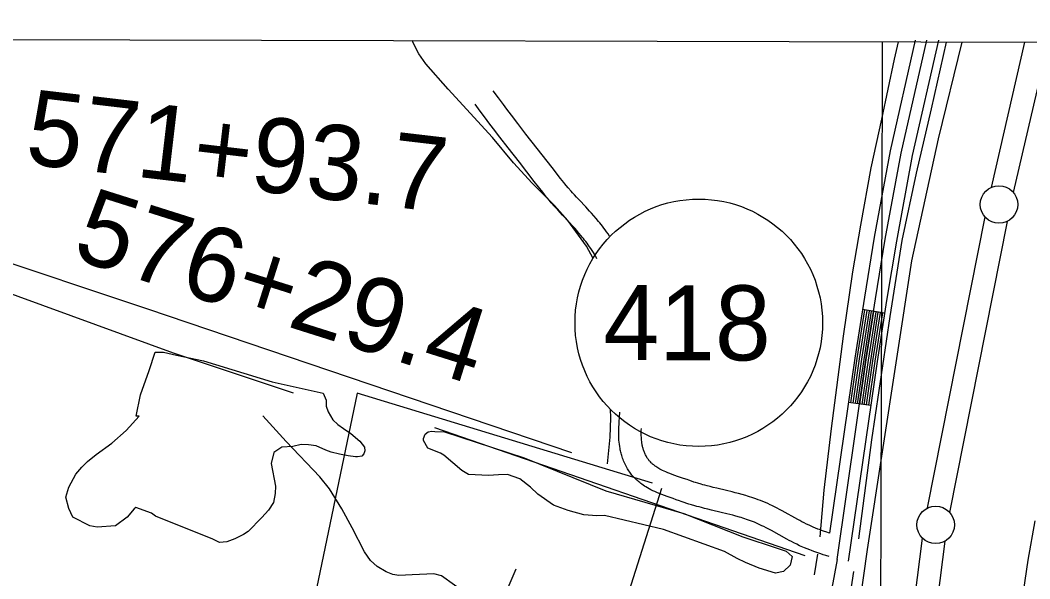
# Model space of a CAD drawing. Extents: x 3161564 to 3199464, y 849354 to 874788.
# Drawn here: x 3175125 to 3176471, y 872262 to 873008 of the extents above; entities that cross this region are included whole.
import ezdxf

# ---------------------------------------------------------------- set-up
doc = ezdxf.new("R2010")
doc.units = 0
for name, color, linetype in [('V-GRID-FRAM', 7, 'Continuous'), ('V-GRID-MAJR', 7, 'Continuous'), ('V-LEVE-TOET', 7, 'Continuous'), ('V-ROAD-CNTR', 7, 'Continuous'), ('V-ROAD-IDEN', 7, 'Continuous'), ('V-SITE-OTLN', 7, 'Continuous'), ('V-SITE-VEGE', 7, 'Continuous'), ('V-SURV-IDEN', 7, 'Continuous'), ('V-SURV-LINE', 7, 'Continuous'), ('V-TOPO-SHOR', 7, 'Continuous')]:
    doc.layers.add(name, color=color, linetype=linetype)

msp = doc.modelspace()

# ---------------------------------------------------------------- linework, layer by layer
at = {"layer": 'V-GRID-FRAM'}
msp.add_lwpolyline([(3165819.245, 873007.562), (3197186.656, 872920.878), (3197144.3310000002, 854733.305), (3165761.0470000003, 854820.033), (3165819.245, 873007.562)], dxfattribs=at)
at = {"layer": 'V-GRID-MAJR'}
msp.add_spline([(3176222.1410000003, 854791.1240000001), (3176239.768, 860850.5530000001), (3176257.404, 866913.068), (3176275.039, 872975.626), (3176275.048, 872978.667)], degree=3, dxfattribs=at)
at = {"layer": 'V-LEVE-TOET'}
for points in [[(3175669.738000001, 869514.5099999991), (3175708.198000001, 869561.856999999), (3175732.372000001, 869595.7699999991), (3175748.332000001, 869623.0369999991), (3175762.058000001, 869648.878999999), (3175775.258000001, 869685.574999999), (3175784.889000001, 869728.035999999), (3175832.198000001, 869934.2939999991), (3175892.899000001, 870206.655999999), (3175926.2690000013, 870366.307999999), (3175967.069000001, 870549.3459999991), (3176018.859000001, 870778.4959999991), (3176047.926000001, 870905.3269999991), (3176080.453000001, 871065.533999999), (3176105.082000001, 871234.712999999), (3176159.337000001, 871580.123999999), (3176184.862000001, 871793.4339999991), (3176216.7690000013, 872030.7399999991), (3176255.034000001, 872301.2399999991), (3176314.084000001, 872686.621999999), (3176349.676000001, 872849.050999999), (3176380.955172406, 872978.3746601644)], [(3176478.148000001, 872339.542999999), (3176468.909000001, 872287.337999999), (3176458.986000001, 872221.037999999), (3176408.313000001, 871944.309999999), (3176379.415000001, 871710.888999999), (3176378.688000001, 871680.0319999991), (3176378.135000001, 871643.724999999), (3176375.205000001, 871570.586999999), (3176373.527000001, 871541.283999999), (3176341.085000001, 871290.329999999), (3176335.283000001, 871235.1249999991), (3176329.973000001, 871198.3509999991), (3176324.869000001, 871172.4659999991), (3176274.335000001, 870917.665999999), (3176234.616000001, 870710.0129999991), (3176228.691000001, 870677.5789999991), (3176219.067000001, 870634.459999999), (3176203.726000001, 870577.062999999), (3176141.878000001, 870249.145999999), (3176018.202000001, 869784.677999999), (3175980.086000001, 869653.8209999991), (3175937.514000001, 869556.466999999)]]:
    msp.add_lwpolyline(points, dxfattribs=at)
at = {"layer": 'V-ROAD-CNTR'}
for p, q in [((3176277.8544074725, 872616.703738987), (3176248.2194667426, 872621.3707296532)), ((3176259.2014447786, 872493.302985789), (3176229.508504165, 872497.584977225))]:
    msp.add_line(p, q, dxfattribs=at)
for points in [[(3176318.6973257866, 872981.0900102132), (3176285.174392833, 872833.2033059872), (3176263.9574352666, 872717.9045365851), (3176250.857461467, 872638.126696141), (3176238.009487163, 872556.535859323), (3176204.363554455, 872323.2053259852)], [(3176214.436534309, 872287.967396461), (3176252.8424574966, 872554.2988637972), (3176265.6674318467, 872635.744700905), (3176278.735405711, 872715.3315417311), (3176299.8713634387, 872830.186312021), (3176334.068295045, 872981.0480102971)], [(3176349.4392643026, 872981.0050103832), (3176314.5683340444, 872827.1693180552), (3176293.513376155, 872712.7585468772), (3176280.4774022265, 872633.3627056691), (3176267.675427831, 872552.0618682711), (3176229.282504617, 872285.826400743)], [(3175911.8898007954, 872718.2979710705), (3175911.0551410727, 872719.5705332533), (3175909.096144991, 872722.4485274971), (3175907.170148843, 872725.183522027), (3175905.2801526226, 872727.7845168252), (3175903.429156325, 872730.2615118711), (3175901.621159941, 872732.6205071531), (3175899.8521634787, 872734.8735026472), (3175898.1271669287, 872737.0244983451), (3175896.426170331, 872739.104494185), (3175893.1701768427, 872742.9864864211), (3175890.075183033, 872746.572479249), (3175887.160188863, 872749.8704726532), (3175884.411194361, 872752.9274665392), (3175879.2992045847, 872758.5034553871), (3175870.4242223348, 872768.0264363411), (3175867.1412289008, 872771.556429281), (3175864.3062345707, 872774.626423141), (3175861.8562394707, 872777.3064177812), (3175859.755243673, 872779.6344131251), (3175856.0932509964, 872783.7704048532), (3175853.419256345, 872786.8713986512), (3175851.449260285, 872789.2093939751), (3175850.0092631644, 872790.9523904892), (3175847.850267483, 872793.6233851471), (3175845.700271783, 872796.3643796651), (3175834.414294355, 872810.9333505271), (3175814.5603340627, 872836.436299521), (3175799.7143637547, 872855.551261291), (3175788.6513858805, 872869.902232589), (3175780.4124023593, 872880.6882110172), (3175774.271414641, 872888.7961948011), (3175769.6984237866, 872894.8801826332), (3175762.8684374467, 872904.0471642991), (3175756.0744510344, 872913.2811458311)], [(3175894.2321747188, 872689.3745936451), (3175893.059177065, 872691.5365893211), (3175892.219178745, 872693.0345863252), (3175890.886181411, 872695.3345817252), (3175889.517184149, 872697.5985771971), (3175887.8051875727, 872700.317571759), (3175886.1091909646, 872702.9025665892), (3175884.4301943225, 872705.3705616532), (3175882.768197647, 872707.7295569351), (3175881.128200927, 872709.988552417), (3175879.5092041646, 872712.1535480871), (3175877.9152073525, 872714.2325439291), (3175876.3502104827, 872716.2275399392), (3175874.811213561, 872718.1465361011), (3175873.322216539, 872719.9685324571), (3175870.322222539, 872723.5425253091), (3175867.4772282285, 872726.8385187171), (3175864.766233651, 872729.9085125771), (3175862.201238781, 872732.7595068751), (3175857.269248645, 872738.139496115), (3175848.468266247, 872747.5844772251), (3175845.139272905, 872751.1624700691), (3175842.212278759, 872754.3304637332), (3175839.650283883, 872757.1364581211), (3175837.3912884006, 872759.6364531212), (3175833.5012961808, 872764.0304443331), (3175830.5873020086, 872767.4094375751), (3175828.4153063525, 872769.9874324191), (3175826.779309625, 872771.9664284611), (3175824.378314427, 872774.937422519), (3175822.0383191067, 872777.922416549), (3175810.7203417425, 872792.5333873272), (3175790.878381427, 872818.0203363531), (3175775.9884112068, 872837.1912980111), (3175764.8514334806, 872851.6382691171), (3175756.5344501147, 872862.5262473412), (3175750.323462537, 872870.7262309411), (3175745.6784718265, 872876.9062185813), (3175738.758485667, 872886.1952000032), (3175731.910499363, 872895.5011813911)], [(3176251.182460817, 872620.903730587), (3176240.976481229, 872556.0888602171), (3176232.4784982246, 872497.1559780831)], [(3176254.146454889, 872620.4367315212), (3176243.942475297, 872555.6408611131), (3176235.4474922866, 872496.7279789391)], [(3176257.109448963, 872619.969732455), (3176246.909469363, 872555.1938620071), (3176238.4164863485, 872496.2989797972)], [(3176260.0734430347, 872619.503733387), (3176249.875463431, 872554.7458629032), (3176241.3864804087, 872495.8709806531)], [(3176263.036437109, 872619.0367343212), (3176252.8424574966, 872554.2988637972), (3176244.3554744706, 872495.442981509)], [(3176265.999431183, 872618.569735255), (3176255.809451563, 872553.851864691), (3176247.3244685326, 872495.0149823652)], [(3176268.963425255, 872618.103736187), (3176258.7754456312, 872553.403865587), (3176250.294462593, 872494.5869832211)], [(3176271.926419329, 872617.6367371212), (3176261.742439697, 872552.9568664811), (3176253.2634566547, 872494.1579840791)], [(3176274.8904134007, 872617.169738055), (3176264.7084337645, 872552.5088673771), (3176256.232450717, 872493.729984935)], [(3175935.0020931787, 872409.1311541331), (3175934.0840950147, 872410.7121509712), (3175933.106096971, 872412.5231473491), (3175932.1690988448, 872414.3841436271), (3175931.310100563, 872416.2011399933), (3175930.514102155, 872417.995136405), (3175929.781103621, 872419.7641328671), (3175929.103104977, 872421.5111293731), (3175928.482106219, 872423.229125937), (3175927.913107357, 872424.9181225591), (3175927.390108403, 872426.5831192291), (3175926.914109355, 872428.2201159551), (3175926.4791102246, 872429.830112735), (3175926.0861110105, 872431.4081095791), (3175925.729111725, 872432.9591064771), (3175925.4051123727, 872434.487103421), (3175925.104112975, 872436.0411003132), (3175924.618113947, 872438.916094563), (3175924.228114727, 872441.7420889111), (3175923.927115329, 872444.459083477), (3175923.7041157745, 872447.0760782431), (3175923.546116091, 872449.5920732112), (3175923.444116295, 872452.0100683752), (3175923.387116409, 872454.3330637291), (3175923.370116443, 872456.5630592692), (3175923.383116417, 872458.7140549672), (3175923.424116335, 872460.8180507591), (3175923.5631160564, 872464.724042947), (3175923.758115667, 872468.3820356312), (3175923.984115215, 872471.785028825), (3175924.4651142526, 872477.9460165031), (3175925.0240227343, 872484.6772464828)], [(3175960.9440412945, 872424.199123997), (3175960.2600426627, 872425.3761216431), (3175959.706043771, 872426.4031195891), (3175959.129044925, 872427.5461173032), (3175958.588046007, 872428.6911150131), (3175958.0880470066, 872429.8211127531), (3175957.625047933, 872430.936110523), (3175957.199048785, 872432.0351083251), (3175956.806049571, 872433.1231061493), (3175956.441050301, 872434.2021039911), (3175956.1080509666, 872435.2671018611), (3175955.800051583, 872436.322099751), (3175955.519052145, 872437.3660976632), (3175955.260052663, 872438.4040955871), (3175955.023053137, 872439.431093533), (3175954.809053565, 872440.447091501), (3175954.6240539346, 872441.399089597), (3175954.274054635, 872443.468085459), (3175954.002055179, 872445.442081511), (3175953.787055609, 872447.385077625), (3175953.624055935, 872449.292073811), (3175953.5060561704, 872451.1660700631), (3175953.428056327, 872453.0060663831), (3175953.385056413, 872454.8150627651), (3175953.370056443, 872456.5910592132), (3175953.381056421, 872458.326055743), (3175953.4140563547, 872459.9900524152), (3175953.510001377, 872462.6876141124)], [(3176204.363554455, 872323.2053259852), (3176199.6255639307, 872324.781322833), (3176197.502568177, 872325.509321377), (3176193.722575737, 872326.860318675), (3176190.928581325, 872327.9013165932), (3176188.862585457, 872328.695315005), (3176185.721591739, 872329.9413125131), (3176182.6045979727, 872331.2253099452), (3176180.7136017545, 872332.0333083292), (3176178.887605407, 872332.8413067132), (3176177.1516088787, 872333.633305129), (3176173.678615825, 872335.2833018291), (3176170.4556222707, 872336.8832986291), (3176167.426628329, 872338.4402955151), (3176164.5736340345, 872339.947292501), (3176161.928639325, 872341.3722896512), (3176141.222680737, 872352.8642666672), (3176138.4946861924, 872354.345263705), (3176133.764695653, 872356.849258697), (3176130.134702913, 872358.7062549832), (3176127.373708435, 872360.0722522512), (3176125.251712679, 872361.0942502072), (3176122.0867190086, 872362.5672472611), (3176118.859725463, 872364.0012443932), (3176115.5817320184, 872365.384241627), (3176112.3907384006, 872366.6602390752), (3176109.297744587, 872367.8372367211), (3176106.2977505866, 872368.9272345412), (3176103.390756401, 872369.936232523), (3176100.5707620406, 872370.876230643), (3176097.838767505, 872371.7502288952), (3176095.1937727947, 872372.5672272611), (3176092.6047779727, 872373.3402257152), (3176087.685787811, 872374.743222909), (3176083.0527970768, 872375.9982203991), (3176078.7198057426, 872377.1232181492), (3176074.6548138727, 872378.1442161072), (3176067.1318289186, 872379.972212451), (3176054.075855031, 872383.081206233), (3176049.2488646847, 872384.2512038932), (3176045.0588730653, 872385.2932018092), (3176041.421880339, 872386.2241999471), (3176038.262886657, 872387.057198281), (3176035.516892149, 872387.805196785), (3176033.152896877, 872388.4681954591), (3176028.9729052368, 872389.6881930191), (3176025.895911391, 872390.6321911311), (3176023.6329159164, 872391.3541896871), (3176020.2039227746, 872392.497187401), (3176016.734929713, 872393.7181849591), (3176014.4219343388, 872394.5461833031), (3176009.8409435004, 872396.140180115), (3176005.5649520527, 872397.6031771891), (3176001.6189599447, 872398.9581744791), (3175997.9909672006, 872400.2311719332), (3175994.6599738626, 872401.439169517), (3175991.6139799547, 872402.5931672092), (3175988.834985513, 872403.7011649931), (3175986.303990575, 872404.7671628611), (3175984.0009951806, 872405.795160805), (3175981.909999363, 872406.7851588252), (3175980.0120031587, 872407.7401569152), (3175978.2880066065, 872408.659155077), (3175976.730009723, 872409.540153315), (3175975.314012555, 872410.3901516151), (3175974.0310151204, 872411.2031499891), (3175972.866017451, 872411.9831484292), (3175971.808019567, 872412.7291469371), (3175970.849021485, 872413.4411455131), (3175969.969023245, 872414.1261441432), (3175969.1720248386, 872414.7771428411), (3175968.4440262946, 872415.3981415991), (3175967.7790276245, 872415.9891404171), (3175967.174028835, 872416.5501392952), (3175966.669029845, 872417.0371383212), (3175965.6010319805, 872418.126136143), (3175964.755033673, 872419.0491342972), (3175964.0460350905, 872419.8741326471), (3175963.4410363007, 872420.6191311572), (3175962.9260373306, 872421.286129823), (3175962.5320381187, 872421.8211287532), (3175961.7370397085, 872422.964126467), (3175961.205040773, 872423.7841248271), (3175960.748041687, 872424.526123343)], [(3176203.700555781, 872292.1113881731), (3176199.607563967, 872293.304385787), (3176195.9575712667, 872294.424383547), (3176192.783577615, 872295.4403815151), (3176190.0215831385, 872296.3593796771), (3176187.586588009, 872297.195378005), (3176183.436596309, 872298.6783750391), (3176180.310602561, 872299.843372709), (3176177.952607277, 872300.7493708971), (3176174.4776142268, 872302.1273681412), (3176170.9966211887, 872303.561365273), (3176168.749625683, 872304.521363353), (3176166.589630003, 872305.4773614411), (3176164.4856342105, 872306.4373595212), (3176160.572642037, 872308.2973558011), (3176156.927649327, 872310.1053521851), (3176153.562656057, 872311.8363487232), (3176150.453662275, 872313.4773454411), (3176147.5326681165, 872315.0523422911), (3176126.7907096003, 872326.564319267), (3176124.320714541, 872327.9033165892), (3176119.914723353, 872330.2373119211), (3176116.6507298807, 872331.906308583), (3176114.2097347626, 872333.1143061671), (3176112.4137383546, 872333.980304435), (3176109.666743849, 872335.2573018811), (3176106.9357493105, 872336.471299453), (3176104.179754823, 872337.634297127), (3176101.484760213, 872338.712294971), (3176098.843765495, 872339.7172929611), (3176096.257770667, 872340.655291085), (3176093.7267757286, 872341.5342893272), (3176091.254780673, 872342.3582876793), (3176088.838785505, 872343.1322861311), (3176086.477790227, 872343.861284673), (3176084.2007947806, 872344.5402833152), (3176079.6498038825, 872345.8392807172), (3176075.360812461, 872347.0002783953), (3176071.293820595, 872348.0572762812), (3176067.458828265, 872349.0202743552), (3176060.115842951, 872350.804270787), (3176047.065869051, 872353.9112645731), (3176042.0968789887, 872355.117262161), (3176037.7228877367, 872356.203259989), (3176033.873895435, 872357.188258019), (3176030.492902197, 872358.081256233), (3176027.526908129, 872358.889254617), (3176024.9009133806, 872359.6242531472), (3176020.3709224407, 872360.948250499), (3176016.937929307, 872362.000248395), (3176014.330934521, 872362.832246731), (3176010.4799422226, 872364.1152441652), (3176006.7009497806, 872365.446241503), (3176004.4399543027, 872366.254239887), (3176000.0549630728, 872367.780236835), (3175995.8369715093, 872369.2232339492), (3175991.780979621, 872370.616231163), (3175987.9069873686, 872371.975228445), (3175984.2279947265, 872373.3112257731), (3175980.744001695, 872374.6312231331), (3175977.4570082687, 872375.9412205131), (3175974.3660144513, 872377.2432179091), (3175971.467020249, 872378.5372153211), (3175968.7500256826, 872379.823212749), (3175966.210030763, 872381.100210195), (3175963.840035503, 872382.365207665), (3175961.626039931, 872383.6182051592), (3175959.568044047, 872384.8522026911), (3175957.653047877, 872386.0652002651), (3175955.8740514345, 872387.257197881), (3175954.222054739, 872388.421195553), (3175952.687057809, 872389.561193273), (3175951.271060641, 872390.664191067), (3175949.954063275, 872391.737188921), (3175948.736065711, 872392.7761868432), (3175947.6070679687, 872393.781184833), (3175946.5600700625, 872394.7521828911), (3175945.543072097, 872395.7331809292), (3175943.827075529, 872397.4821774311), (3175942.313078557, 872399.1351741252), (3175941.020081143, 872400.6401711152), (3175939.923083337, 872401.9911684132), (3175938.984085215, 872403.2061659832), (3175938.138086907, 872404.3511636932), (3175936.8310895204, 872406.2341599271), (3175935.845091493, 872407.7521568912), (3175935.198092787, 872408.8041547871)]]:
    msp.add_lwpolyline(points, dxfattribs=at)
msp.add_spline([(3176214.436534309, 872287.967396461), (3176116.8077295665, 871676.8626186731), (3176098.393766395, 871490.9449905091), (3176090.6737818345, 871415.8731406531), (3176074.078815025, 871299.531373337), (3176058.2058467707, 871187.518597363), (3176040.2208827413, 871070.2398319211), (3175999.5479640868, 870899.038174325), (3175937.9290873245, 870603.4047655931), (3175884.9331933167, 870365.7572408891), (3175824.806313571, 870091.4527894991), (3175789.966383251, 869942.7890868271), (3175763.646435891, 869809.981352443), (3175731.110500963, 869705.4375615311), (3175702.3135585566, 869636.881698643), (3175675.0326131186, 869598.4667754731), (3175630.9917012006, 869537.224897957), (3175579.3838044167, 869482.4070075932), (3175530.4689022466, 869432.7421069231), (3175484.1399949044, 869377.7432169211), (3175466.8220295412, 869337.1482981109), (3175448.870065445, 869288.948394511), (3175412.8401375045, 869163.3436457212), (3175354.171254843, 868894.673183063), (3175303.0893570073, 868660.035652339), (3175288.269386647, 868568.9528345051), (3175271.5774200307, 868449.007074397), (3175249.1094649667, 868331.0303103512), (3175221.754519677, 868196.0075803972), (3175175.815611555, 868026.9179185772), (3175130.084703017, 867866.9672384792), (3175087.9327873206, 867676.3666196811), (3175040.187882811, 867488.062996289), (3174985.3579924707, 867232.2935078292), (3174937.599087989, 866993.627985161), (3174859.654243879, 866658.7776548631), (3174804.595353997, 866380.105212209), (3174764.5064341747, 866230.530511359), (3174736.375490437, 866088.411795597)], degree=3, dxfattribs=at)
at = {"layer": 'V-ROAD-IDEN'}
msp.add_circle((3176030.072069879, 872603.8419210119), 165.0000000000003, dxfattribs=at)
msp.add_circle((3176030.072069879, 872603.8419210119), 165.0000000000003, dxfattribs=at)
at = {"layer": 'V-SITE-OTLN'}
msp.add_line((3175785.991, 872275.1680000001), (3175752.328, 872195.2170000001), dxfattribs=at)
msp.add_lwpolyline([(3175968.549, 872389.917), (3175574.492, 872510.112), (3175480.198, 872055.106), (3175663.648, 872029.779), (3175692.557, 872127.408), (3175879.125, 872061.9400000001), (3175981.029, 872383.1560000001)], dxfattribs=at)
at = {"layer": 'V-SITE-VEGE'}
for points in [[(3175369.827000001, 872552.9959999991), (3175461.486000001, 872524.9879999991), (3175529.143000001, 872509.743999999), (3175533.438000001, 872500.5839999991), (3175533.565000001, 872492.479999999), (3175536.217000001, 872485.165999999), (3175542.439000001, 872474.430999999), (3175548.882000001, 872468.0229999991), (3175556.464000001, 872462.707999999), (3175566.116000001, 872456.0989999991), (3175578.211000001, 872445.8119999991), (3175584.345000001, 872437.871999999), (3175584.812000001, 872432.974999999), (3175583.618000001, 872428.9469999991), (3175580.767000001, 872426.0669999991), (3175575.301000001, 872425.052999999), (3175572.229000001, 872425.1129999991), (3175562.755000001, 872426.410999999), (3175551.204000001, 872428.7259999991), (3175540.221000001, 872431.309999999), (3175532.727000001, 872433.9679999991), (3175519.987000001, 872439.7969999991), (3175509.812000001, 872440.9709999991), (3175500.182000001, 872441.432999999), (3175488.957000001, 872438.7139999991), (3175474.134000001, 872437.8779999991), (3175463.800000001, 872430.670999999), (3175460.167000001, 872415.935999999), (3175465.735000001, 872385.655999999), (3175465.549000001, 872375.8829999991), (3175462.946000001, 872363.9189999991), (3175456.331000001, 872353.9879999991), (3175447.618000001, 872343.9569999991), (3175429.520000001, 872325.1639999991), (3175423.1610000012, 872321.3759999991), (3175411.600000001, 872315.7289999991), (3175400.906000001, 872311.601999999), (3175391.253000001, 872310.809999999), (3175382.255000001, 872315.0349999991), (3175306.046000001, 872346.0129999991), (3175300.359000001, 872349.844999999), (3175279.478000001, 872357.5549999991), (3175277.567000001, 872355.662999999), (3175268.001000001, 872344.2989999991), (3175252.731000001, 872332.962999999), (3175227.997000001, 872331.182999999), (3175218.498000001, 872333.1329999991), (3175195.733000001, 872344.6549999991), (3175190.087000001, 872356.094999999), (3175186.355000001, 872371.327999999), (3175190.226000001, 872384.621999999), (3175199.819000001, 872401.6939999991), (3175207.472000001, 872411.1619999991), (3175215.117000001, 872418.7309999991), (3175226.576000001, 872428.184999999), (3175247.570000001, 872443.2949999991), (3175266.672000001, 872460.317999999), (3175283.883000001, 872479.2499999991), (3175280.078000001, 872479.2679999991), (3175285.925000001, 872507.7679999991), (3175297.496000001, 872540.0399999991), (3175305.221000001, 872564.726999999), (3175316.635000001, 872564.6719999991), (3175333.729000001, 872560.7829999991)], [(3175690.896000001, 872458.3289999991), (3175797.231000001, 872423.6159999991), (3175906.325000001, 872379.6309999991), (3176010.235000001, 872349.432999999), (3176088.567000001, 872318.464999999), (3176134.512000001, 872303.2039999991), (3176146.445000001, 872299.064999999), (3176154.416000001, 872292.207999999), (3176151.817000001, 872280.5219999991), (3176142.992000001, 872271.8919999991), (3176132.4820000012, 872269.9949999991), (3176110.675000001, 872276.5569999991), (3176092.5190000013, 872284.0279999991), (3176081.030000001, 872289.555999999), (3176064.302000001, 872298.672999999), (3175982.869000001, 872328.1649999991), (3175904.165000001, 872346.846999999), (3175894.234000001, 872346.1969999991), (3175876.658000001, 872347.5099999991), (3175856.100000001, 872353.4899999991), (3175836.403000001, 872360.7089999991), (3175815.306000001, 872375.2189999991), (3175805.844000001, 872384.4809999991), (3175791.3940000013, 872395.7919999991), (3175774.877000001, 872401.275999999), (3175763.273000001, 872400.7989999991), (3175749.709000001, 872399.9389999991), (3175723.197000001, 872401.560999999), (3175714.078000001, 872406.7629999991), (3175690.020000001, 872427.055999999), (3175685.602000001, 872429.7969999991), (3175668.831000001, 872436.6819999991), (3175663.300000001, 872446.841999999), (3175663.072000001, 872449.6419999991), (3175665.272000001, 872455.045999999), (3175669.108000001, 872458.466999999), (3175674.013000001, 872459.3489999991), (3175678.057000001, 872458.9949999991)]]:
    msp.add_lwpolyline(points, close=True, dxfattribs=at)
at = {"layer": 'V-SURV-LINE'}
for points in [[(3176420.1276262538, 872784.528622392), (3176464.8248930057, 872978.1430674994)], [(3176495.594311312, 872978.0580365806), (3176449.362843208, 872777.797915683)], [(3176334.961640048, 872356.7337155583), (3176411.6628914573, 872745.0012723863)], [(3176441.091384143, 872739.1734068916), (3176364.390191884, 872350.9061494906)], [(3176231.613587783, 871553.9519130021), (3176328.40646125, 872316.2856187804)], [(3176358.1663880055, 872312.4978963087), (3176261.373543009, 871550.1644147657)]]:
    msp.add_lwpolyline(points, dxfattribs=at)
for centre in [(3176430.249380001, 872761.6871400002), (3176345.80387, 872334.2200999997)]:
    msp.add_circle(centre, 25, dxfattribs=at)
at = {"layer": 'V-TOPO-SHOR'}
for p, q in [((3175677.7202956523, 872464.0549217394), (3176171.549826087, 872293.5238608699)), ((3176184.133000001, 872267.5659999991), (3176188.825000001, 872295.172999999))]:
    msp.add_line(p, q, dxfattribs=at)
for points in [[(3175860.685913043, 872430.3039826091), (3175295.801773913, 872622.1514260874), (3174837.4995478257, 872774.9188347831), (3174478.673773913, 872906.3698608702), (3174421.8300869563, 872924.1335130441), (3174407.6191652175, 872927.6862434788), (3174364.9864, 872938.3444347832), (3174347.2227478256, 872984.5299304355)], [(3175889.3555761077, 872689.6842796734), (3175880.312000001, 872705.905999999), (3175855.480000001, 872740.346999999), (3175837.603000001, 872760.417999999), (3175808.021000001, 872790.0229999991), (3175783.171000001, 872817.2109999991), (3175754.892000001, 872850.836999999), (3175696.201000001, 872915.555999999), (3175666.333000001, 872949.4559999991), (3175657.024000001, 872962.6229999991), (3175649.342000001, 872977.498999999), (3175648.3136237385, 872980.3993188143)], [(3176191.962000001, 872318.395999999), (3176197.432000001, 872380.420999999), (3176206.841000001, 872462.5909999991), (3176222.791000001, 872585.810999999), (3176235.333000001, 872671.7209999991), (3176246.197000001, 872733.8899999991), (3176259.913000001, 872810.584999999), (3176273.896000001, 872875.635999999), (3176290.862000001, 872955.7009999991), (3176296.4497782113, 872978.6081912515)], [(3176359.6981062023, 872978.4334041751), (3176340.002000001, 872889.2999999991), (3176319.802000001, 872803.476999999), (3176300.627000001, 872713.587999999), (3176284.906000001, 872612.0539999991), (3176260.267000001, 872447.4569999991), (3176243.049000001, 872315.6209999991)], [(3174462.6864869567, 872879.7243826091), (3175329.552713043, 872563.5313739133), (3175489.4255826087, 872510.2404173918)], [(3175823.861000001, 872124.6429999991), (3175808.241000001, 872134.4979999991), (3175793.886000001, 872146.535999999), (3175783.108000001, 872159.6079999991), (3175756.156000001, 872205.0939999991), (3175745.533000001, 872220.003999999), (3175737.005000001, 872228.9879999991), (3175721.8030000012, 872241.5319999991), (3175686.981000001, 872266.214999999), (3175676.741000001, 872269.1039999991), (3175667.658000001, 872268.297999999), (3175648.038000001, 872267.567999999), (3175630.376000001, 872266.8019999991), (3175622.192000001, 872268.184999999), (3175613.191000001, 872271.7849999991), (3175601.313000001, 872278.6299999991), (3175592.402000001, 872286.886999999), (3175584.650000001, 872298.062999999), (3175567.984000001, 872330.2429999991), (3175554.127000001, 872355.5049999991), (3175537.728000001, 872382.4099999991), (3175525.039000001, 872398.2139999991), (3175479.981000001, 872445.270999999), (3175449.021000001, 872479.6839999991)], [(3175908.484000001, 872415.675999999), (3175911.8570000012, 872451.2719999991), (3175912.842000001, 872477.229999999), (3175912.468266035, 872488.7442106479)], [(3176236.156000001, 872272.1889999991), (3176212.182000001, 872113.6449999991), (3176168.342000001, 871799.9709999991), (3176144.238000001, 871634.6299999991)]]:
    msp.add_lwpolyline(points, dxfattribs=at)

# ---------------------------------------------------------------- texts
at = {"layer": 'V-ROAD-IDEN'}
msp.add_text('418', height=100.00000200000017, rotation=359.8416625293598, dxfattribs=at).set_placement((3175902.769079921, 872554.1935340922))
at = {"layer": 'V-SURV-IDEN'}
for s, height, rotation, p in [('571+93.7', 100.00000000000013, 353.2944001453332, (3175130.325491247, 872816.3196476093)), ('576+29.4', 100.00000000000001, 342.43562868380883, (3175192.2752272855, 872690.4351688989))]:
    msp.add_text(s, height=height, rotation=rotation, dxfattribs=at).set_placement(p)

doc.saveas('drawing.dxf')
